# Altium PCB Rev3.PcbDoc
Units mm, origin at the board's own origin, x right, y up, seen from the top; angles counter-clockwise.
Board outline 76.2 x 63.5 mm, 2 copper layers (Top Layer, Bottom Layer); 85 components, 38 nets, 172 pads, 17 vias.
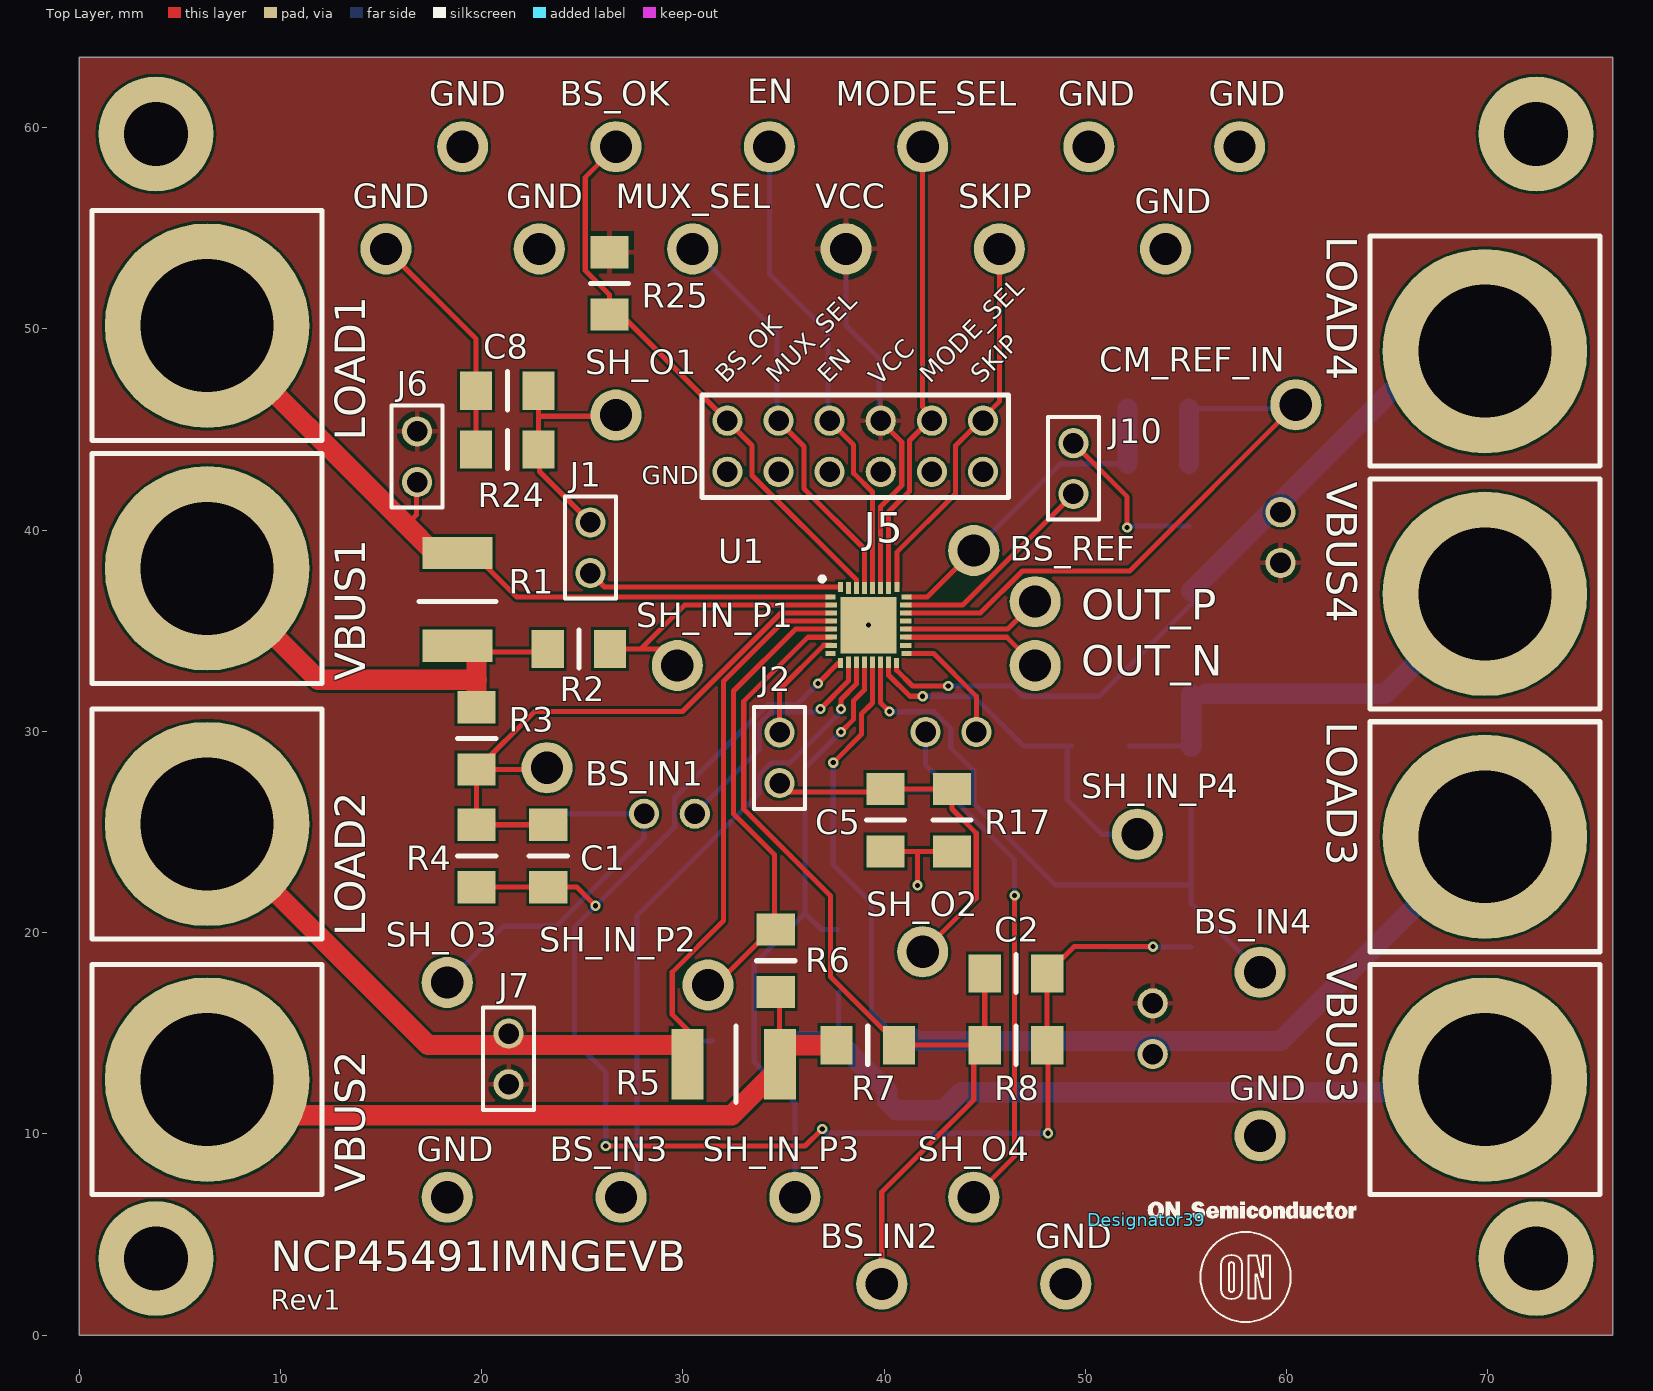
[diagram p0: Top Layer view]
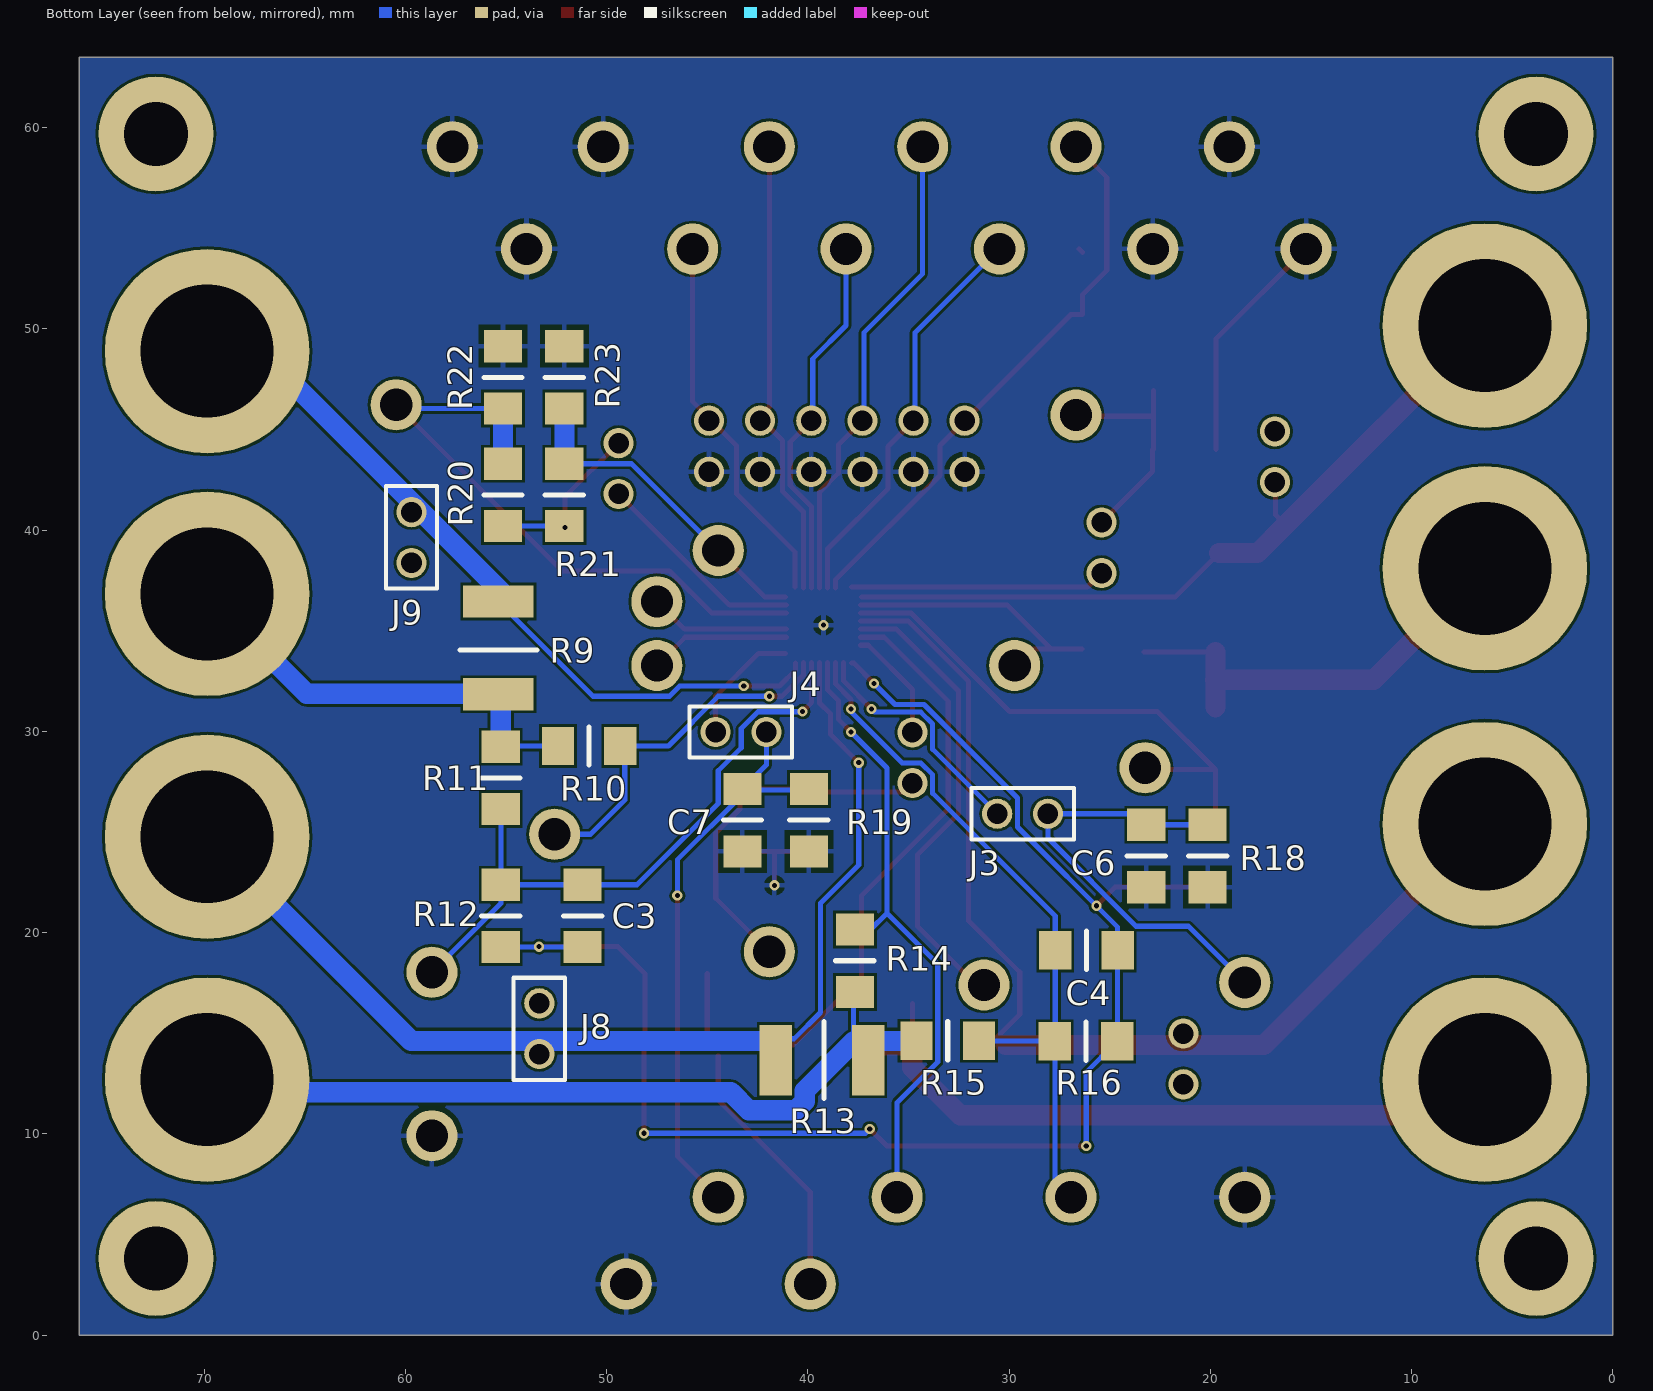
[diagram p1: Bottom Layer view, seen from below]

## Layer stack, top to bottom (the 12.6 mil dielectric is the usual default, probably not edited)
Top Solder: solder mask 0.0102, Solder Resist, Dk 3.5
Top Layer: signal copper 0.0356
Dielectric 1: dielectric 0.32, FR-4, Dk 4.8
Bottom Layer: signal copper 0.0356
Bottom Solder: solder mask 0.0102, Solder Resist, Dk 3.5

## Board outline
0,0 76.2,0 76.2,63.5 0,63.5

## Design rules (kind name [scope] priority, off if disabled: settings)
Clearance [All] p1: gap=0.127 ignorepadtopadclearanceinfootprint=FALSE except(0: Arc-Hole Track-Hole SMDPad-Hole THPad-Hole Via-Hole Fill-Hole Poly-Hole Region-Hole Text-Hole)
HoleSize [All] p1: absolutevalues=TRUE maxlimit=7 minlimit=0.025 maxpercent=80.000 minpercent=20.000
PolygonConnect [All] p1: connectstyle=Relief reliefconductorwidth=0.254 reliefentries=4 polygonreliefangle="90 Angle" airgapwidth=0.254
RoutingVias [All] p1: holewidth=0.711 width=1.27 viastyle="Through Hole" minholewidth=0.711 minwidth=1.27 maxholewidth=0.711 maxwidth=1.27
SilkToSolderMaskClearance [IsPad] p1: minsilkscreentomaskgap=0.05 clearancetoexposedcopper=TRUE
SolderMaskExpansion [All] p1: expansion=0.076
UnRoutedNet [All] p1: checkbadconnections=TRUE
Width [All] p1: maxlimit=2.54 minlimit=0.254 preferedwidth=0.254
27 further rules are at their usual default settings.

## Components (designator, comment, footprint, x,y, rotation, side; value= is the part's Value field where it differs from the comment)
BS_IN1 "Test_Point" TEST_POINT 23.241,28.194 r90 top
BS_IN2 "Test_Point" TEST_POINT 39.878,2.54 r90 top
BS_IN3 "Test_Point" TEST_POINT 26.924,6.858 r90 top
BS_IN4 "Test_Point" TEST_POINT 58.674,18.034 r90 top
BS_OK "DIG_IN" TEST_POINT 26.67,59.055 r0 top
BS_REF "Test_Point" TEST_POINT 44.45,38.989 r90 top
C1 "Cap" CAP1206 22.352,26.162 r270 top
C2 "Cap" CAP1206 44.196,17.018 r0 top
C3 "Cap" CAP1206 52.138,23.183 r270 bottom
C4 "Cap" CAP1206 28.5,18.172 r180 bottom
C5 "Cap" CAP1206 39.116,27.94 r270 top
C6 "Cap" CAP1206 24.13,26.162 r270 bottom
C7 "Cap" CAP1206 44.196,27.94 r270 bottom
C8 "Cap" CAP1206 23.622,47.879 r180 top
CM_REF_IN "Test_Point" TEST_POINT 60.452,46.228 r90 top
Designator39 "Comment" ONLogoText 53.047,5.743 r0 top
EN "DIG_IN" TEST_POINT 34.29,59.055 r0 top
GND "GND" TEST_POINT 50.165,59.055 r0 top
GND "GND" TEST_POINT 19.05,59.055 r90 top (schematic designator TP29)
GND "GND" TEST_POINT 22.86,53.975 r90 top (schematic designator TP30)
GND "GND" TEST_POINT 49.022,2.54 r90 top (schematic designator TP32)
GND "GND" TEST_POINT 58.674,9.906 r90 top (schematic designator TP33)
GND "GND" TEST_POINT 15.24,53.975 r90 top (schematic designator TP34)
GND "GND" TEST_POINT 53.975,53.975 r90 top (schematic designator TP35)
GND "GND" TEST_POINT 18.288,6.858 r90 top (schematic designator TP36)
GND "GND" TEST_POINT 57.658,59.055 r0 top
J1 "952-2262-ND" JUMPER 25.4,40.386 r270 top
J2 "952-2262-ND" JUMPER 34.798,27.432 r90 top
J3 "952-2262-ND" JUMPER 28.067,25.908 r0 bottom
J4 "952-2262-ND" JUMPER 44.577,29.972 r180 bottom
J5 "609-3237-ND" 6X2HEADER 39.827,42.901 r0 top
J6 "952-2262-ND" JUMPER 16.789,44.907 r270 top (schematic designator J3)
J7 "952-2262-ND" JUMPER 21.336,14.986 r270 top (schematic designator J3)
J8 "952-2262-ND" JUMPER 53.34,13.97 r90 bottom (schematic designator J5)
J9 "952-2262-ND" JUMPER 59.69,40.894 r270 bottom (schematic designator J5)
J10 "952-2262-ND" JUMPER 49.403,44.323 r270 top
LOAD1 "J587-ND" BANNANA_CONNECTOR 6.35,50.165 r0 top
LOAD2 "J587-ND" BANNANA_CONNECTOR 6.35,25.4 r0 top
LOAD3 "J587-ND" BANNANA_CONNECTOR 69.85,24.765 r0 top
LOAD4 "J587-ND" BANNANA_CONNECTOR 69.85,48.895 r0 top
MODE_SEL "DIG_IN" TEST_POINT 41.91,59.055 r0 top
MUX_SEL "DIG_IN" TEST_POINT 30.48,53.975 r0 top
OUT_N "Diff_Out" TEST_POINT 47.498,33.274 r0 top (schematic designator DIFF_OUT_N)
OUT_P "Diff_Out" TEST_POINT 47.498,36.449 r0 top (schematic designator DIFF_OUT_P)
R1 "=" RES2512 18.796,38.862 r270 top
R2 "311-1.24FRDKR-ND" RES1206 22.479,33.147 r0 top
R3 "RMCF1206FT118KDKR-ND" RES1206 18.796,32.004 r270 top
R4 "Supplier Part Number 2" RES1206 18.796,26.162 r270 top
R5 "P5.0MCT-ND" RES2512 30.226,13.462 r0 top
R6 "RMCF1206FT12R4CT-ND" RES1206 35.56,16.256 r90 top
R7 "RMCF1206FT57K6DKR-ND" RES1206 36.83,13.462 r0 top
R8 "Supplier Part Number 2" RES1206 44.196,13.462 r0 top
R9 "Res_1" RES2512 55.372,36.449 r270 bottom
R10 "Res" RES1206 48.514,30.226 r0 bottom
R11 "Res" RES1206 56.202,30.041 r270 bottom
R12 "Res" RES1206 56.202,23.183 r270 bottom
R13 "P5.0MCT-ND" RES2512 41.591,13.667 r180 bottom
R14 "311-2.49FRTR-ND" RES1206 38.608,20.955 r270 bottom
R15 "311-1.30MFRTR-ND" RES1206 35.395,13.679 r180 bottom
R16 "311-10.0KFRTR-ND" RES1206 28.523,13.651 r180 bottom
R17 "RNCP1206FTD100RCT-ND" RES1206 42.418,27.94 r270 top
R18 "RNCP1206FTD100RCT-ND" RES1206 21.082,26.162 r270 bottom
R19 "NP" RES1206 40.894,27.94 r270 bottom
R20 "Supplier Part Number 2" RES1206 51.145,39.401 r90 bottom
R21 "Supplier Part Number 2" RES1206 54.193,39.401 r90 bottom
R22 "RMCF1206FT1K00DKR-ND" RES1206 51.145,45.243 r90 bottom
R23 "Supplier Part Number 2" RES1206 54.193,45.243 r90 bottom
R24 "RNCP1206FTD100RCT-ND" RES1206 23.622,44.958 r180 top
R25 "RMCF1206FT100KDKR-ND" RES1206 25.4,54.61 r270 top
SH_IN_P1 "Test_Point" TEST_POINT 29.718,33.274 r90 top
SH_IN_P2 "Test_Point" TEST_POINT 31.242,17.399 r90 top
SH_IN_P3 "Test_Point" TEST_POINT 35.56,6.858 r90 top
SH_IN_P4 "Test_Point" TEST_POINT 52.578,24.892 r90 top
SH_O1 "Test_Point" TEST_POINT 26.67,45.72 r90 top
SH_O2 "Test_Point" TEST_POINT 41.91,19.05 r90 top
SH_O3 "Test_Point" TEST_POINT 18.288,17.526 r90 top
SH_O4 "Test_Point" TEST_POINT 44.45,6.858 r90 top
SKIP "DIG_IN" TEST_POINT 45.72,53.975 r0 top
U1 "NCP45491" NCP45491 39.218,35.281 r270 top
VBUS1 "J587-ND" BANNANA_CONNECTOR 6.35,38.1 r0 top
VBUS2 "J587-ND" BANNANA_CONNECTOR 6.35,12.7 r0 top
VBUS3 "J587-ND" BANNANA_CONNECTOR 69.85,12.7 r0 top
VBUS4 "J587-ND" BANNANA_CONNECTOR 69.85,36.83 r0 top
VCC "DIG_IN" TEST_POINT 38.1,53.975 r0 top
? "Comment" ONLogoBol 57.912,2.794 r0 top

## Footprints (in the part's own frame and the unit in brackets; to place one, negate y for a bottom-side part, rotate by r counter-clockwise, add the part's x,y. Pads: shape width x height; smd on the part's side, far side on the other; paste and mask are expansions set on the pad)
6X2HEADER [mm]
  round 1.5 hole 1.02: 0(-7.62,2.54) 1(-5.08,2.54) 2(-2.54,2.54) 3(0,2.54) 4(2.54,2.54) 5(5.08,2.54) 6(-7.62,0) 7(-5.08,0) 8(-2.54,0) 9(0,0) 10(2.54,0) 11(5.08,0)
  silkscreen extent -8.89,-1.27 6.35,3.81
BANNANA_CONNECTOR [mil] "Bannana_Connector"
  round 400 hole 260: 1(0,0)
  silkscreen extent -225,-225 225,225
CAP1206 [mm] "SMD size 1206"
  rect 1.6x1.9 smd mask+0.1: 1(0.8,0.95) 2(3.9,0.95)
  silkscreen extent 2.35,0 2.35,1.9
JUMPER [mm] "Jumper"
  round 1.5 hole 1.02: 1(0,0) 2(2.52,0)
  silkscreen extent -1.29,-1.27 3.79,1.27
NCP45491 [mm]
  rect 0.25x0.5 smd: 1(-1.4,-1.89) 8(1.4,-1.89) 17(1.4,1.89) 24(-1.4,1.89)
  rect 0.25x0.58 smd: 2(-1,-1.85) 3(-0.6,-1.85) 4(-0.2,-1.85) 5(0.2,-1.85) 6(0.6,-1.85) 7(1,-1.85) 18(1,1.85) 19(0.6,1.85) 20(0.2,1.85) 21(-0.2,1.85) 22(-0.6,1.85) 23(-1,1.85)
  rect 0.5x0.25 smd: 9(1.89,-1.4) 16(1.89,1.4) 25(-1.89,1.41) 32(-1.89,-1.4)
  rect 0.58x0.25 smd: 10(1.85,-1) 11(1.85,-0.6) 12(1.85,-0.2) 13(1.85,0.2) 14(1.85,0.6) 15(1.85,1) 26(-1.85,1) 27(-1.85,0.6) 28(-1.85,0.2) 29(-1.85,-0.2) 30(-1.85,-0.6) 31(-1.85,-1)
  rect 2.8x2.8 smd mask+0.25: 33(0,0)
  silkscreen extent -2.4,-2.4 -2.2,-2.2
ONLogoBol [mm]
  silkscreen extent -2.2,-2.14 2.28,2.34
ONLogoText [mm]
  silkscreen extent 0.06,0.05 10.41,0.89
RES1206 [mm]
  rect 1.6x1.9 smd mask+0.1: 1(0.8,0.95) 2(3.9,0.95)
  silkscreen extent 2.35,0 2.35,1.9
RES2512 [mm]
  rect 1.6x3.5 smd: 1(0,0) 2(4.6,0)
  silkscreen extent 2.4,-1.9 2.4,1.91
TEST_POINT [mil] "Test_Point"
  round 100 hole 63: 1(0,0)

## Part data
C1 C2 C3 C4 C5 C6 C7 C8 R9 R10 R11 R12: "No Placement"
GND GND GND GND GND GND GND GND GND: "GND Test Point"
J1 J2 J3 J4 J6 J7 J8 J9 J10: library part Jumper, "Jumper"
J5: library part 6x2Header, "6x2 Header"
LOAD1 LOAD2 LOAD3 LOAD4 VBUS1 VBUS2 VBUS3 VBUS4: library part Banana_Connector, "Interconnect"
R1 R5 R13: library part "Res 0.005", "Resistor 5m"
R2: library part "Res 1.24", "Resistor 1.24"
R3: library part "Res 118k", "Resistor 118K"
R4 R8: library part "Res 2k", "Resistor 2K"
R6: library part "Res 12.4", "Resistor 12.4"
R7: library part "Res 57.6k", "Resistor 57.6K"
R14: library part "Res 2.5", "Resistor 2.5"
R15: library part "Res 1.3M", "Resistor 1.3M"
R16: library part "Res 10k", "Resistor 10K"
R17 R18 R24: library part "Res 100", "Resistor 100"
R19: library part Res, "No Placement"
R20 R21 R23: library part "Res 6.34k", "Resistor 6.34K"
R22: library part "Res 1k", "Resistor 1k"
R25: library part "Res 100k", "Resistor 100K"

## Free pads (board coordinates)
  round 5.715 hole 3.175 unplated: ""(3.81,3.81) ""(3.81,59.69) ""(72.39,3.81) ""(72.39,59.69)

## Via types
v1: diameter 0.508, hole 0.254, Top Layer to Bottom Layer, 17 vias

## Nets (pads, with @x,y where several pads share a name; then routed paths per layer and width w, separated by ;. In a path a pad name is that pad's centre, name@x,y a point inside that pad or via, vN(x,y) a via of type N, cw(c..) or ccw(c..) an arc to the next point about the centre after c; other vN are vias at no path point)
BS_OK: BS_OK.1 J5.0 R25.2 U1.30 | length 29
  Top Layer w0.254: BS_OK.1 25.146,57.531 25.146,52.905 26.35,51.701 R25.2 26.92,50.71 J5.0@32.133,45.497 ; J5.0@31.746,45.884 J5.0@32.133,45.497 ; U1.30 38.618,37.532 33.426,42.723 33.426,44.204 J5.0@32.133,45.497
EN: EN.1 J5.2 U1.28 | length 24.2
  Top Layer w0.254: J5.2@37.084,45.626 38.481,44.229 38.481,42.827 39.418,41.89 U1.28
  Bottom Layer w0.254: EN.1 34.29,52.738 37.213,49.815 J5.2@37.213,45.497
GND: C5.2 C6.2 C7.2 C8.2 GND.1 J5.6 J5.7 J5.8 J5.9 J5.10 J5.11 R17.2 R18.2 R19.2 R22.2 R23.2 R24.2 U1.33 | length 16.8
  Top Layer w0.254: GND.1@15.24,53.975 19.722,49.493 C8.2 R24.2 ; C5.2 41.656,24.04 ; v1(41.656,22.352) 41.656,24.04 ; R17.2 41.656,24.04
  other v1: 39.218,35.281
GND_FET_1: C1.2 C2.2 C3.2 C4.2 R4.2 R8.2 R12.2 R16.2 U1.9 | length 77.4
  Top Layer w0.254: R4.2 C1.2 24.728,22.262 v1(25.654,21.336) ; v1(26.162,9.398) 36.068,9.398 v1(36.92,10.25) ; v1@36.703,32.385 37.709,33.391 U1.9 ; v1(48.133,10.033) 48.133,14.375 R8.2 C2.2 49.432,19.304 v1(53.35,19.304)
  Bottom Layer w0.254: R16.2@24.6,14.624 C4.2 24.6,20.272 29.583,25.255 29.583,26.696 34.224,31.337 35.665,31.337 v1(36.713,32.385) ; R16.2@24.728,14.496 26.162,13.062 v1(26.162,9.398) ; v1(36.92,10.25) 37.137,10.033 v1(48.133,10.033) ; C3.2 R12.2
LOAD_1: J6.2 LOAD1.1 R1.1 U1.1 | length 38.9
  Top Layer w0.254: 16.25,40.265 16.262,40.265 16.764,40.767 J6.2@16.764,42.387 ; R1.1@19.558,38.862 21.739,36.681 U1.1
  Top Layer w1: LOAD1.1 16.25,40.265 17.653,38.862 R1.1@19.558,38.862
LOAD_2: J7.1 LOAD2.1 R5.1 U1.4 | length 54.1
  Top Layer w0.254: R5.1@30.574,14.826 29.464,15.936 29.464,18.034 32.004,20.574 32.004,32.481 35.003,35.481 U1.4
  Top Layer w1: LOAD2.1 17.338,14.412 R5.1@30.16,14.412
LOAD_3: J8.1 LOAD3.1 R13.1 U1.13 | length 59.1
  Top Layer w0.254: v1(37.465,28.448) 38.862,29.845 38.862,30.861 39.418,31.417 U1.13
  Top Layer w1.016: LOAD3.1@69.85,21.336 LOAD3.1 LOAD3.1@69.85,25.4
  Bottom Layer w0.254: v1(37.465,28.448) 37.465,23.368 39.37,21.463 39.37,16.038 40.676,14.732 R13.1@41.529,14.732
  Bottom Layer w1.016: R13.1@41.529,14.732 41.644,14.617 J8.1@53.34,14.617 ; J8.1@53.34,13.863 J8.1@53.34,14.617 ; LOAD3.1 59.702,14.617 J8.1@53.34,14.617
LOAD_4: J9.1 LOAD4.1 R9.1 U1.16 | length 37.1
  Top Layer w0.254: U1.16 40.618,33.042 41.402,32.258 v1(43.18,32.258)
  Bottom Layer w0.254: v1(43.18,32.258) 45.089,32.258 46.359,32.258 46.867,31.75 50.673,31.75 R9.1
  Bottom Layer w1.016: R9.1@55.252,36.964 67.183,48.895 LOAD4.1
MODE_SEL: J5.4 MODE_SEL.1 U1.26 | length 23
  Top Layer w0.254: U1.26 40.218,40.903 41.25,41.935 41.25,44.454 42.418,45.622 41.91,46.13 MODE_SEL.1
MUX_SEL: J5.1 MUX_SEL.1 U1.29 | length 20.4
  Top Layer w0.254: MUX_SEL.1 MUX_SEL.1@30.513,53.975 ; J5.1@34.673,45.497 36.017,44.153 36.017,42.062 39.018,39.062 U1.29
  Bottom Layer w0.254: MUX_SEL.1 30.513,53.975 34.673,49.815 J5.1@34.673,45.497
NetBS_IN1_1: BS_IN1.1 C1.1 R3.2 R4.1 U1.3 | length 30.5
  Top Layer w0.254: BS_IN1.1@23.151,28.104 R3.2 ; C1.1 R4.1 R3.2 ; U1.3 34.865,35.881 29.972,30.988 22.63,30.988 R3.2
NetBS_IN2_1: BS_IN2.1 C2.1 R7.2 R8.1 U1.6 | length 47
  Top Layer w0.254: U1.6 36.205,34.681 33.02,31.496 33.02,26.141 37.338,21.823 37.338,17.804 R7.2 R8.1 C2.1 ; BS_IN2.1 39.878,7.112 44.45,11.684 R8.1@44.45,13.866
NetBS_IN3_1: BS_IN3.1 C4.1 R15.2 R16.1 U1.11 | length 35.7
  Top Layer w0.254: v1(37.846,31.115) 37.846,31.592 38.599,32.345 ; 38.618,32.364 U1.11
  Bottom Layer w0.254: BS_IN3.1 27.723,7.657 R16.1 ; R15.2@31.49,14.624 27.7,14.624 C4.1 27.7,20.832 33.794,26.926 33.794,27.848 34.382,28.436 35.304,28.436 37.846,30.978 v1(37.846,31.115)
NetBS_IN4_1: BS_IN4.1 C3.1 R11.2 R12.1 U1.14 | length 32.2
  Top Layer w0.254: U1.14 39.818,31.429 v1(40.259,30.988)
  Bottom Layer w0.254: v1(40.259,30.988) 40.247,30.976 42.473,30.976 43.307,30.142 43.307,29.188 44.45,28.045 44.45,26.416 48.483,22.383 C3.1 R12.1 ; R11.2 R12.1 ; BS_IN4.1 55.252,21.456 R12.1
NetBS_REF_1: BS_REF.1 R20.2 R22.1 U1.24 | length 16.5
  Top Layer w0.254: U1.24 42.142,36.681 BS_REF.1
  Bottom Layer w0.254: BS_REF.1 48.762,43.301 R20.2
  Bottom Layer w1: R20.2 R22.1
NetC5_1: C5.1 J2.1 R17.1 SH_O2.1 | length 18.2
  Top Layer w0.254: J2.1@34.798,26.985 C5.1@40.043,26.985 ; C5.1 R17.1 43.368,26.149 44.572,24.945 44.572,21.712 SH_O2.1
NetC6_1: C6.1 J3.1 R18.1 SH_O3.1 | length 21.3
  Bottom Layer w0.254: SH_O3.1 21.082,20.32 23.689,20.32 28.067,24.698 J3.1 C6.1@23.726,25.908 ; R18.1 C6.1
NetC7_1: C7.1 J4.2 R19.1 SH_O4.1 | length 28.8
  Top Layer w0.254: SH_O4.1 46.482,8.89 v1(46.482,21.844)
  Bottom Layer w0.254: R19.1@40.13,27.086 C7.1@43.178,27.086 ; J4.2 42.057,28.329 C7.1 43.246,26.858 46.482,23.622 v1(46.482,21.844)
NetC8_1: C8.1 J1.1 R24.1 SH_O1.1 | length 11.4
  Top Layer w0.254: R24.1 C8.1 ; 22.822,45.659 SH_O1.1@26.609,45.659 ; R24.1@22.868,43.962 22.868,44.008 22.868,42.918 J1.1
NetCM_REF_IN_1: CM_REF_IN.1 R21.2 R23.1 U1.22 | length 31.5
  Top Layer w0.254: U1.22 44.774,35.881 46.867,37.973 52.197,37.973 CM_REF_IN.1
  Bottom Layer w0.254: R23.1 CM_REF_IN.1@60.267,46.043
  Bottom Layer w1: R21.2 R23.1
NetJ1_2: J1.2 U1.32 | length 12.7
  Top Layer w0.254: J1.2 26.095,37.171 U1.32
NetJ2_2: J2.2 U1.7 | length 5.6
  Top Layer w0.254: J2.2 34.798,32.085 36.972,34.26 ; 36.993,34.281 U1.7
NetJ3_2: J3.2 U1.10 | length 12
  Top Layer w0.254: v1@36.83,31.115 38.218,32.503 U1.10
  Bottom Layer w0.254: J3.2 33.794,29.115 33.794,30.368 34.382,30.956 36.681,30.956 v1(36.84,31.115)
NetJ4_1: J4.1 U1.17 | length 6.1
  Top Layer w0.254: U1.17 42.446,33.881 44.577,31.75 J4.1
NetJ10_1: J10.1 R20.1 R21.1 | length 8.4
  Top Layer w0.254: J10.1 52.07,41.656 v1(52.07,40.132)
  Bottom Layer w0.254: R20.1@52.026,40.132 v1(52.07,40.132) ; R20.1 R21.1
NetJ10_2: J10.2 U1.23 | length 10.6
  Top Layer w0.254: U1.23 43.897,36.281 J10.2@49.403,41.787
NetOUT_N_1: OUT_N.1 U1.19 | length 7
  Top Layer w0.254: U1.19 46.091,34.681 OUT_N.1
NetOUT_P_1: OUT_P.1 U1.20 | length 7
  Top Layer w0.254: U1.20 46.13,35.081 OUT_P.1
NetR2_2: R2.2 SH_IN_P1.1 U1.2 | length 14
  Top Layer w0.254: R2.2 27.903,34.097 ; SH_IN_P1.1 28.895,34.097 27.903,34.097 ; U1.2 30.087,36.281 27.903,34.097
NetR6_2: R6.2 SH_IN_P2.1 U1.5 | length 23.2
  Top Layer w0.254: SH_IN_P2.1 31.623,17.399 34.544,20.32 34.544,23.876 32.512,25.908 32.512,32.004 35.589,35.081 U1.5
NetR10_1: R10.1 SH_IN_P4.1 U1.15 | length 17.8
  Top Layer w0.254: U1.15 40.218,32.807 41.275,31.75 v1(41.91,31.75)
  Bottom Layer w0.254: v1(41.91,31.75) 44.45,31.75 46.924,29.276 R10.1 ; R10.1@49.094,29.056 49.094,26.598 50.8,24.892 SH_IN_P4.1
NetR14_1: R14.1 SH_IN_P3.1 U1.12 | length 31.6
  Top Layer w0.254: v1@37.846,29.972 38.481,30.607 38.481,31.532 39.018,32.068 U1.12
  Bottom Layer w0.254: SH_IN_P3.1 35.56,11.555 33.541,13.574 33.541,18.445 36.067,20.971 ; R14.1 36.883,20.155 36.067,20.971 ; v1(37.856,29.972) 36.067,28.183 36.067,20.971
SKIP: J5.5 SKIP.1 U1.25 | length 18.9
  Top Layer w0.254: U1.25 40.628,38.9 43.536,41.808 43.536,44.2 45.72,46.384 SKIP.1
VBUS_1: R1.2 R2.1 R3.1 VBUS1.1 | length 22
  Top Layer w0.254: R1.2@19.746,33.946 R2.1@23.279,33.946
  Top Layer w1: R3.1 19.746,32.573 R1.2@19.746,33.946
  Top Layer w1.016: VBUS1.1 11.877,32.573 16.51,32.573 19.746,32.573
VBUS_2: R5.2 R6.1 R7.1 VBUS2.1 | length 35.9
  Top Layer w0.254: R5.2@34.798,14.412 R6.1@34.798,16.482
  Top Layer w1.016: VBUS2.1 8.128,10.922 32.423,10.922 34.798,13.297 R5.2@34.798,14.097 ; R5.2@34.798,14.412 R7.1
VBUS_3: R13.2 R14.2 R15.1 VBUS3.1 | length 39.7
  Bottom Layer w0.254: R13.2@37.719,14.986 R14.2@37.719,17.055
  Bottom Layer w1.016: R15.1@34.607,14.617 37.691,14.617 40.156,12.152 40.156,11.626 40.606,11.176 42.926,11.176 43.815,12.065 69.215,12.065 VBUS3.1
VBUS_4: R9.2 R10.2 R11.1 VBUS4.1 | length 23.8
  Top Layer w1.016: VBUS4.1@69.112,38.1 69.85,38.1 VBUS4.1 VBUS4.1@69.85,36.552
  Bottom Layer w0.254: R10.2@52.194,29.272 R11.1@55.245,29.272
  Bottom Layer w1.016: R11.1 R9.2@55.252,31.856 ; R9.2@56.007,31.877 64.897,31.877 VBUS4.1
VCC: J5.3 J6.1 J7.2 J8.2 J9.2 R25.1 U1.27 VCC.1 | length 18.6
  Top Layer w0.254: R25.1 R25.1@26.515,53.975 ; U1.27 39.818,41.164 40.869,42.215 40.869,44.381 39.827,45.423 J5.3
  Bottom Layer w0.254: VCC.1 38.1,50.165 39.753,48.512 J5.3@39.753,45.497
pads on no net: U1.8 U1.18 U1.21 U1.31

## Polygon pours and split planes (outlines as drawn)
GND on Bottom Layer "Bottom Layer-GND" (solid, pour order 26): 0,63.5 76.2,63.5 76.2,0 0,0
VCC on Top Layer "Bottom Layer-GND" (solid, pour order 28): 0,0 0,63.5 76.2,63.5 76.2,0

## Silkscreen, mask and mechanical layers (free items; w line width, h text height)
Top Overlay:
  text "BS_OK" at 32.131,47.244 h0.91 r45
  text "MUX_SEL" at 34.671,47.244 h0.91 r45
  text "EN" at 37.211,47.244 h0.91 r45
  text "MODE_SEL" at 42.291,47.244 h0.91 r45
  text "SKIP" at 44.831,47.244 h0.91 r45
  text "VCC" at 39.751,47.117 h0.91 r45
  text "GND" at 27.94,42.291 h0.91
  text "NCP45491IMNGEVB" at 9.525,3.175 h1.52
  text "Rev1" at 9.525,1.27 h1
Mechanical 1:
  lines w0.254: 0,0 0,63.5 76.25,63.5 76.25,0 0,0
